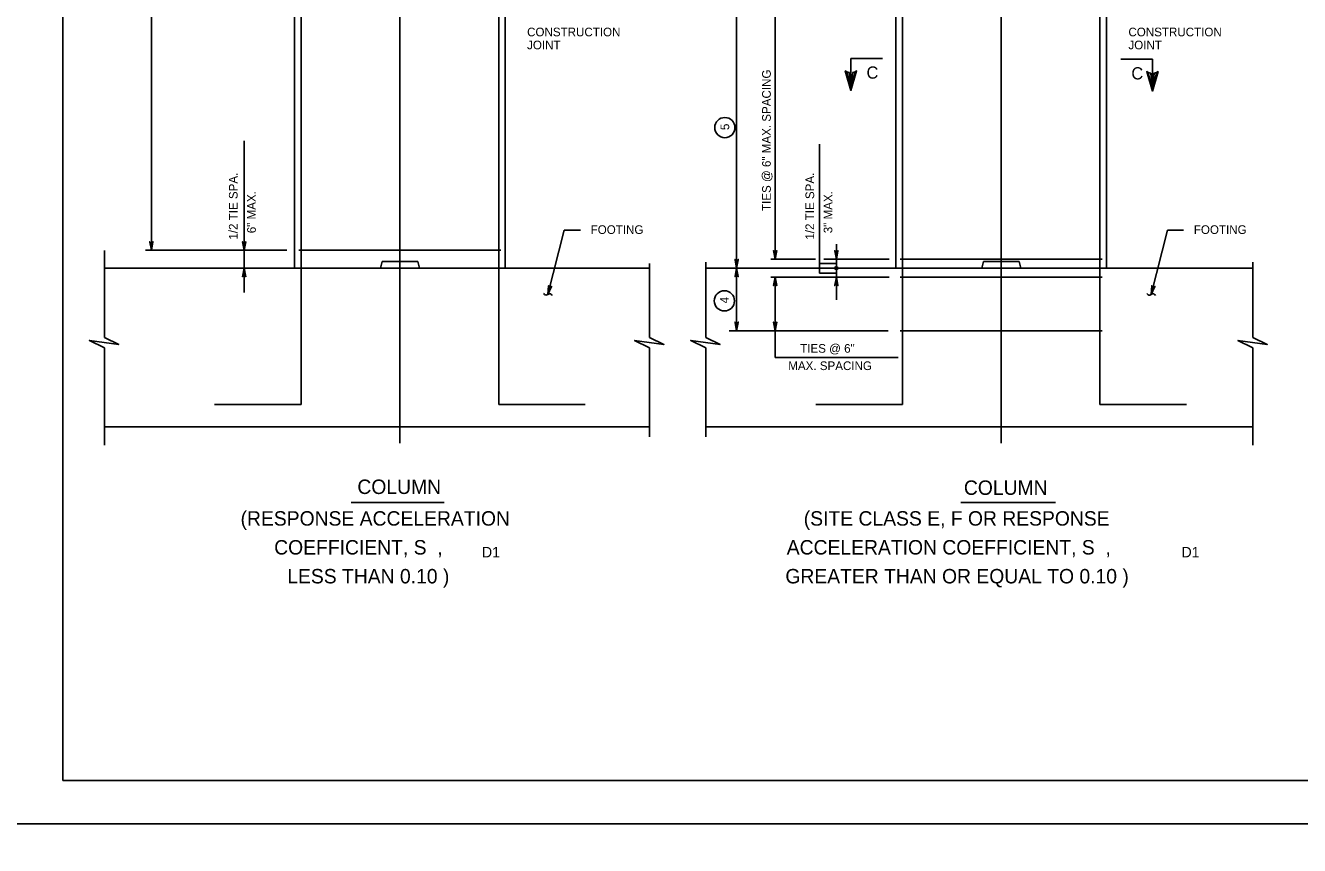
# Model space of a CAD drawing. Extents: x 646165 to 651486, y 296916 to 299292.
# Drawn here: x 649816.7 to 650257.8, y 298096.8 to 298380.6 of the extents above; entities that cross this region are included whole.
import ezdxf

# ---------------------------------------------------------------- set-up
doc = ezdxf.new("R2010")
doc.units = 0
for name, color, linetype in [('1', 7, 'Continuous'), ('2', 7, 'Continuous'), ('50', 7, 'Continuous'), ('51', 7, 'Continuous'), ('52', 7, 'Continuous'), ('53', 7, 'Continuous'), ('54', 7, 'Continuous'), ('PLT-BNDY', 7, 'Continuous')]:
    doc.layers.add(name, color=color, linetype=linetype)

msp = doc.modelspace()

# ---------------------------------------------------------------- linework, layer by layer
at = {"layer": '1'}
for p, q in [((650102.47, 298369.22), (650113.39, 298369.22)), ((650102.47, 298358.15), (650102.47, 298369.22)), ((650206.88, 298368.95), (650195.96, 298368.95)), ((650206.88, 298357.88), (650206.88, 298368.95))]:
    msp.add_line(p, q, dxfattribs=at)
for points in [[(650103.94, 298364.57), (650103.09, 298364.33), (650102.47, 298358.15), (650103.94, 298364.57), (650104.45, 298364.9), (650102.47, 298358.15), (650101.91, 298364.33), (650101.07, 298364.55), (650102.47, 298358.15), (650100.52, 298364.9), (650101.07, 298364.55)], [(650205.41, 298364.3), (650206.26, 298364.07), (650206.88, 298357.88), (650205.41, 298364.3), (650204.89, 298364.63), (650206.88, 298357.88), (650207.44, 298364.06), (650208.27, 298364.29), (650206.88, 298357.88), (650208.83, 298364.63), (650208.27, 298364.29)]]:
    msp.add_lwpolyline(points, dxfattribs=at)
at = {"layer": '2'}
for p, q in [((649829.59, 298119.25), (649829.59, 298683.25)), ((650615.59, 298119.25), (649829.59, 298119.25))]:
    msp.add_line(p, q, dxfattribs=at)
at = {"layer": '50'}
for p, q in [((649946.33, 298602.2), (649946.33, 298236.03)), ((650154.51, 298602.2), (650154.51, 298236.03))]:
    msp.add_line(p, q, dxfattribs=at)
at = {"layer": '51'}
for p, q in [((649909.88, 298430.58), (649909.88, 298296.63)), ((649982.78, 298430.58), (649982.78, 298296.63)), ((650118.06, 298430.58), (650118.06, 298296.63)), ((650190.96, 298430.58), (650190.96, 298296.63)), ((649844.05, 298296.63), (650032.79, 298296.63)), ((649940.16, 298298.88), (649939.58, 298296.63)), ((649940.16, 298298.88), (649952.5, 298298.88)), ((649952.5, 298298.88), (649953.08, 298296.63)), ((650052.23, 298296.63), (650241.62, 298296.63)), ((650148.34, 298298.88), (650147.76, 298296.63)), ((650148.34, 298298.88), (650160.68, 298298.88)), ((650160.68, 298298.88), (650161.26, 298296.63)), ((649844.05, 298241.73), (650032.79, 298241.73)), ((650052.23, 298241.73), (650241.62, 298241.73))]:
    msp.add_line(p, q, dxfattribs=at)
at = {"layer": '52'}
for p, q in [((649860.29, 298560.63), (649860.29, 298302.78)), ((650076.27, 298560.63), (650076.27, 298299.7)), ((650062.91, 298398.45), (650062.91, 298274.96)), ((649892.42, 298340.72), (649892.42, 298288.23)), ((650091.64, 298339.58), (650091.64, 298294.9)), ((650003.24, 298309.74), (649997.59, 298287.5)), ((650003.24, 298309.74), (650008.83, 298309.74)), ((650212.08, 298309.74), (650206.42, 298287.5)), ((650212.08, 298309.74), (650217.66, 298309.74)), ((649844.05, 298302.74), (649844.05, 298272.55)), ((649858.24, 298302.78), (649907.15, 298302.78)), ((650097.43, 298304.96), (650097.43, 298285.69)), ((650032.79, 298298.2), (650032.79, 298272.55)), ((650052.23, 298298.63), (650052.23, 298272.55)), ((650090.22, 298299.7), (650074.79, 298299.7)), ((650097.43, 298298.23), (650091.64, 298298.23)), ((650115.76, 298299.7), (650093.09, 298299.7)), ((650241.62, 298298.63), (650241.62, 298272.55)), ((650115.76, 298293.54), (650074.79, 298293.54)), ((650076.27, 298293.54), (650076.27, 298265.65)), ((650097.43, 298294.9), (650091.64, 298294.9)), ((650060.29, 298274.96), (650115.33, 298274.96)), ((649844.05, 298269.03), (649844.05, 298235.31)), ((650032.79, 298269.03), (650032.79, 298238.17)), ((650052.23, 298269.03), (650052.23, 298238.17)), ((650241.62, 298269.03), (650241.62, 298235.31)), ((650076.27, 298265.65), (650118.8, 298265.65))]:
    msp.add_line(p, q, dxfattribs=at)
for points in [[(649860.29, 298302.78), (649859.73, 298305.76), (649859.81, 298305.65), (649859.89, 298305.53), (649859.99, 298305.48), (649860.09, 298305.42), (649860.19, 298305.4), (649860.29, 298305.38), (649860.39, 298305.4), (649860.49, 298305.42), (649860.59, 298305.48), (649860.69, 298305.53), (649860.77, 298305.65), (649860.85, 298305.76), (649860.29, 298302.78), (649860.77, 298305.65), (649860.69, 298305.53), (649860.29, 298302.78), (649860.59, 298305.48), (649860.49, 298305.42), (649860.29, 298302.78), (649860.39, 298305.4), (649860.29, 298305.38), (649860.29, 298302.78), (649860.19, 298305.4), (649860.09, 298305.42), (649860.29, 298302.78), (649859.99, 298305.48), (649859.89, 298305.53), (649860.29, 298302.78), (649859.81, 298305.65)], [(649892.42, 298302.78), (649891.86, 298305.76), (649891.94, 298305.65), (649892.02, 298305.53), (649892.12, 298305.48), (649892.22, 298305.42), (649892.32, 298305.4), (649892.42, 298305.38), (649892.52, 298305.4), (649892.62, 298305.42), (649892.72, 298305.48), (649892.82, 298305.53), (649892.9, 298305.65), (649892.98, 298305.76), (649892.42, 298302.78), (649892.9, 298305.65), (649892.82, 298305.53), (649892.42, 298302.78), (649892.72, 298305.48), (649892.62, 298305.42), (649892.42, 298302.78), (649892.52, 298305.4), (649892.42, 298305.38), (649892.42, 298302.78), (649892.32, 298305.4), (649892.22, 298305.42), (649892.42, 298302.78), (649892.12, 298305.48), (649892.02, 298305.53), (649892.42, 298302.78), (649891.94, 298305.65)], [(650076.27, 298299.7), (650075.71, 298302.69), (650075.79, 298302.57), (650075.87, 298302.46), (650075.97, 298302.4), (650076.07, 298302.34), (650076.17, 298302.32), (650076.27, 298302.3), (650076.37, 298302.32), (650076.47, 298302.34), (650076.57, 298302.4), (650076.67, 298302.46), (650076.74, 298302.57), (650076.82, 298302.69), (650076.27, 298299.7), (650076.74, 298302.57), (650076.67, 298302.46), (650076.27, 298299.7), (650076.57, 298302.4), (650076.47, 298302.34), (650076.27, 298299.7), (650076.37, 298302.32), (650076.27, 298302.3), (650076.27, 298299.7), (650076.17, 298302.32), (650076.07, 298302.34), (650076.27, 298299.7), (650075.97, 298302.4), (650075.87, 298302.46), (650076.27, 298299.7), (650075.79, 298302.57)], [(650097.43, 298299.7), (650097.99, 298302.69), (650097.91, 298302.57), (650097.83, 298302.46), (650097.73, 298302.4), (650097.63, 298302.34), (650097.53, 298302.32), (650097.43, 298302.3), (650097.33, 298302.32), (650097.23, 298302.34), (650097.13, 298302.4), (650097.03, 298302.46), (650096.96, 298302.57), (650096.88, 298302.69), (650097.43, 298299.7), (650096.96, 298302.57), (650097.03, 298302.46), (650097.43, 298299.7), (650097.13, 298302.4), (650097.23, 298302.34), (650097.43, 298299.7), (650097.33, 298302.32), (650097.43, 298302.3), (650097.43, 298299.7), (650097.53, 298302.32), (650097.63, 298302.34), (650097.43, 298299.7), (650097.73, 298302.4), (650097.83, 298302.46), (650097.43, 298299.7), (650097.91, 298302.57)], [(649892.42, 298296.63), (649892.98, 298293.64), (649892.9, 298293.76), (649892.82, 298293.87), (649892.72, 298293.93), (649892.62, 298293.99), (649892.52, 298294.01), (649892.42, 298294.03), (649892.32, 298294.01), (649892.22, 298293.99), (649892.12, 298293.93), (649892.02, 298293.87), (649891.94, 298293.76), (649891.86, 298293.64), (649892.42, 298296.63), (649891.94, 298293.76), (649892.02, 298293.87), (649892.42, 298296.63), (649892.12, 298293.93), (649892.22, 298293.99), (649892.42, 298296.63), (649892.32, 298294.01), (649892.42, 298294.03), (649892.42, 298296.63), (649892.52, 298294.01), (649892.62, 298293.99), (649892.42, 298296.63), (649892.72, 298293.93), (649892.82, 298293.87), (649892.42, 298296.63), (649892.9, 298293.76)], [(650062.91, 298296.63), (650063.47, 298299.61), (650063.39, 298299.49), (650063.31, 298299.38), (650063.21, 298299.32), (650063.11, 298299.26), (650063.01, 298299.24), (650062.91, 298299.23), (650062.81, 298299.24), (650062.71, 298299.26), (650062.61, 298299.32), (650062.51, 298299.38), (650062.43, 298299.49), (650062.35, 298299.61), (650062.91, 298296.63), (650062.43, 298299.49), (650062.51, 298299.38), (650062.91, 298296.63), (650062.61, 298299.32), (650062.71, 298299.26), (650062.91, 298296.63), (650062.81, 298299.24), (650062.91, 298299.23), (650062.91, 298296.63), (650063.01, 298299.24), (650063.11, 298299.26), (650062.91, 298296.63), (650063.21, 298299.32), (650063.31, 298299.38), (650062.91, 298296.63), (650063.39, 298299.49)], [(650062.91, 298296.63), (650063.47, 298293.64), (650063.39, 298293.76), (650063.31, 298293.87), (650063.21, 298293.93), (650063.11, 298293.99), (650063.01, 298294.01), (650062.91, 298294.03), (650062.81, 298294.01), (650062.71, 298293.99), (650062.61, 298293.93), (650062.51, 298293.87), (650062.43, 298293.76), (650062.35, 298293.64), (650062.91, 298296.63), (650062.43, 298293.76), (650062.51, 298293.87), (650062.91, 298296.63), (650062.61, 298293.93), (650062.71, 298293.99), (650062.91, 298296.63), (650062.81, 298294.01), (650062.91, 298294.03), (650062.91, 298296.63), (650063.01, 298294.01), (650063.11, 298293.99), (650062.91, 298296.63), (650063.21, 298293.93), (650063.31, 298293.87), (650062.91, 298296.63), (650063.39, 298293.76)], [(650076.27, 298293.54), (650076.82, 298290.56), (650076.74, 298290.68), (650076.67, 298290.79), (650076.57, 298290.85), (650076.47, 298290.91), (650076.37, 298290.93), (650076.27, 298290.94), (650076.17, 298290.93), (650076.07, 298290.91), (650075.97, 298290.85), (650075.87, 298290.79), (650075.79, 298290.68), (650075.71, 298290.56), (650076.27, 298293.54), (650075.79, 298290.68), (650075.87, 298290.79), (650076.27, 298293.54), (650075.97, 298290.85), (650076.07, 298290.91), (650076.27, 298293.54), (650076.17, 298290.93), (650076.27, 298290.94), (650076.27, 298293.54), (650076.37, 298290.93), (650076.47, 298290.91), (650076.27, 298293.54), (650076.57, 298290.85), (650076.67, 298290.79), (650076.27, 298293.54), (650076.74, 298290.68)], [(650097.43, 298293.54), (650096.88, 298290.56), (650096.96, 298290.68), (650097.03, 298290.79), (650097.13, 298290.85), (650097.23, 298290.91), (650097.33, 298290.93), (650097.43, 298290.94), (650097.53, 298290.93), (650097.63, 298290.91), (650097.73, 298290.85), (650097.83, 298290.79), (650097.91, 298290.68), (650097.99, 298290.56), (650097.43, 298293.54), (650097.91, 298290.68), (650097.83, 298290.79), (650097.43, 298293.54), (650097.73, 298290.85), (650097.63, 298290.91), (650097.43, 298293.54), (650097.53, 298290.93), (650097.43, 298290.94), (650097.43, 298293.54), (650097.33, 298290.93), (650097.23, 298290.91), (650097.43, 298293.54), (650097.13, 298290.85), (650097.03, 298290.79), (650097.43, 298293.54), (650096.96, 298290.68)], [(649997.59, 298287.5), (649997.78, 298290.53), (649997.83, 298290.4), (649997.88, 298290.27), (649997.96, 298290.19), (649998.04, 298290.11), (649998.14, 298290.07), (649998.23, 298290.02), (649998.33, 298290.02), (649998.43, 298290.01), (649998.54, 298290.04), (649998.65, 298290.07), (649998.76, 298290.17), (649998.87, 298290.26), (649997.59, 298287.5), (649998.76, 298290.17), (649998.65, 298290.07), (649997.59, 298287.5), (649998.54, 298290.04), (649998.43, 298290.01), (649997.59, 298287.5), (649998.33, 298290.02), (649998.23, 298290.02), (649997.59, 298287.5), (649998.14, 298290.07), (649998.04, 298290.11), (649997.59, 298287.5), (649997.96, 298290.19), (649997.88, 298290.27), (649997.59, 298287.5), (649997.83, 298290.4)], [(650206.42, 298287.5), (650206.62, 298290.53), (650206.66, 298290.4), (650206.71, 298290.27), (650206.8, 298290.19), (650206.88, 298290.11), (650206.97, 298290.07), (650207.06, 298290.02), (650207.16, 298290.02), (650207.27, 298290.01), (650207.38, 298290.04), (650207.49, 298290.07), (650207.59, 298290.17), (650207.7, 298290.26), (650206.42, 298287.5), (650207.59, 298290.17), (650207.49, 298290.07), (650206.42, 298287.5), (650207.38, 298290.04), (650207.27, 298290.01), (650206.42, 298287.5), (650207.16, 298290.02), (650207.06, 298290.02), (650206.42, 298287.5), (650206.97, 298290.07), (650206.88, 298290.11), (650206.42, 298287.5), (650206.8, 298290.19), (650206.71, 298290.27), (650206.42, 298287.5), (650206.66, 298290.4)], [(650062.91, 298274.96), (650062.35, 298277.94), (650062.43, 298277.83), (650062.51, 298277.71), (650062.61, 298277.65), (650062.71, 298277.59), (650062.81, 298277.58), (650062.91, 298277.56), (650063.01, 298277.58), (650063.11, 298277.59), (650063.21, 298277.65), (650063.31, 298277.71), (650063.39, 298277.83), (650063.47, 298277.94), (650062.91, 298274.96), (650063.39, 298277.83), (650063.31, 298277.71), (650062.91, 298274.96), (650063.21, 298277.65), (650063.11, 298277.59), (650062.91, 298274.96), (650063.01, 298277.58), (650062.91, 298277.56), (650062.91, 298274.96), (650062.81, 298277.58), (650062.71, 298277.59), (650062.91, 298274.96), (650062.61, 298277.65), (650062.51, 298277.71), (650062.91, 298274.96), (650062.43, 298277.83)], [(650062.91, 298274.96), (650062.35, 298277.94), (650062.43, 298277.83), (650062.51, 298277.71), (650062.61, 298277.65), (650062.71, 298277.59), (650062.81, 298277.58), (650062.91, 298277.56), (650063.01, 298277.58), (650063.11, 298277.59), (650063.21, 298277.65), (650063.31, 298277.71), (650063.39, 298277.83), (650063.47, 298277.94), (650062.91, 298274.96), (650063.39, 298277.83), (650063.31, 298277.71), (650062.91, 298274.96), (650063.21, 298277.65), (650063.11, 298277.59), (650062.91, 298274.96), (650063.01, 298277.58), (650062.91, 298277.56), (650062.91, 298274.96), (650062.81, 298277.58), (650062.71, 298277.59), (650062.91, 298274.96), (650062.61, 298277.65), (650062.51, 298277.71), (650062.91, 298274.96), (650062.43, 298277.83)], [(650076.27, 298274.96), (650075.71, 298277.94), (650075.79, 298277.83), (650075.87, 298277.71), (650075.97, 298277.65), (650076.07, 298277.59), (650076.17, 298277.58), (650076.27, 298277.56), (650076.37, 298277.58), (650076.47, 298277.59), (650076.57, 298277.65), (650076.67, 298277.71), (650076.74, 298277.83), (650076.82, 298277.94), (650076.27, 298274.96), (650076.74, 298277.83), (650076.67, 298277.71), (650076.27, 298274.96), (650076.57, 298277.65), (650076.47, 298277.59), (650076.27, 298274.96), (650076.37, 298277.58), (650076.27, 298277.56), (650076.27, 298274.96), (650076.17, 298277.58), (650076.07, 298277.59), (650076.27, 298274.96), (650075.97, 298277.65), (650075.87, 298277.71), (650076.27, 298274.96), (650075.79, 298277.83)], [(649844.05, 298269.03), (649838.87, 298271.57), (649849.02, 298270.19), (649844.05, 298272.55)], [(650032.79, 298269.03), (650027.61, 298271.57), (650037.75, 298270.19), (650032.79, 298272.55)], [(650052.23, 298269.03), (650047.05, 298271.57), (650057.19, 298270.19), (650052.23, 298272.55)], [(650241.62, 298269.03), (650236.44, 298271.57), (650246.59, 298270.19), (650241.62, 298272.55)]]:
    msp.add_lwpolyline(points, dxfattribs=at)
for centre, radius in [((650058.84, 298345.26), 3.5), ((650097.43, 298296.63), 0.533), ((650097.43, 298296.63), 0.267), ((650058.67, 298285.28), 3.5)]:
    msp.add_circle(centre, radius, dxfattribs=at)
for points in [[(649999.09, 298287.09), (649998.37, 298287.75), (649996.8, 298287.26), (649996.08, 298287.87)], [(650207.93, 298287.09), (650207.2, 298287.75), (650205.63, 298287.26), (650204.91, 298287.87)]]:
    msp.add_spline(points, degree=3, dxfattribs=at)
at = {"layer": '53'}
for p, q in [((649929.45, 298215.53), (649961.63, 298215.53)), ((650140.56, 298215.53), (650173.34, 298215.53))]:
    msp.add_line(p, q, dxfattribs=at)
at = {"layer": '54'}
for p, q in [((649912.13, 298427.99), (649912.13, 298249.41)), ((649980.53, 298427.99), (649980.53, 298249.41)), ((650120.31, 298427.99), (650120.31, 298249.41)), ((650188.71, 298427.99), (650188.71, 298249.41)), ((649911.38, 298302.78), (649981.28, 298302.78)), ((650119.56, 298299.7), (650189.46, 298299.7)), ((650119.56, 298293.54), (650189.46, 298293.54)), ((650119.56, 298274.96), (650189.46, 298274.96)), ((649882.13, 298249.41), (649912.13, 298249.41)), ((649980.53, 298249.41), (650010.53, 298249.41)), ((650090.31, 298249.41), (650120.31, 298249.41)), ((650188.71, 298249.41), (650218.71, 298249.41))]:
    msp.add_line(p, q, dxfattribs=at)
at = {"layer": 'PLT-BNDY'}
for points in [[(649789.59, 298698.25), (650630.59, 298698.25), (650630.59, 298104.25), (649789.59, 298104.25)], [(649789.59, 298104.25), (650630.59, 298104.25), (650630.59, 297510.25), (649789.59, 297510.25)]]:
    msp.add_lwpolyline(points, close=True, dxfattribs=at)

# ---------------------------------------------------------------- texts
at = {"layer": '1'}
for p in [(650107.88, 298362.2), (650199.58, 298361.94)]:
    msp.add_text('C', height=4.23, dxfattribs=at).set_placement(p)
at = {"layer": '53'}
for s, height, p in [('CONSTRUCTION', 3, (649990.37, 298376.86)), ('CONSTRUCTION', 3, (650198.55, 298376.86)), ('JOINT', 3, (649990.37, 298372.36)), ('JOINT', 3, (650198.55, 298372.36)), ('FOOTING', 3, (650012.37, 298308.45)), ('FOOTING', 3, (650221.2, 298308.45)), ('TIES @ 6"', 3, (650084.91, 298267.33)), ('MAX. SPACING', 3, (650080.78, 298261.33)), ('COLUMN', 5, (649931.61, 298218.43)), ('COLUMN', 5, (650141.59, 298218.13)), ('(RESPONSE ACCELERATION', 5, (649891.17, 298207.48)), ('(SITE CLASS E, F OR RESPONSE', 5, (650086.15, 298207.48)), ('COEFFICIENT, S  ,', 5, (649902.81, 298197.48)), ('D1', 3.63, (649974.76, 298196.49)), ('ACCELERATION COEFFICIENT, S  ,', 5, (650080.26, 298197.48)), ('D1', 3.63, (650216.95, 298196.49)), ('LESS THAN 0.10 )', 5, (649907.34, 298187.48)), ('GREATER THAN OR EQUAL TO 0.10 )', 5, (650079.79, 298187.48))]:
    msp.add_text(s, height=height, dxfattribs=at).set_placement(p)
for s, p in [('TIES @ 6" MAX. SPACING', (650074.74, 298316.39)), ('5', (650060.34, 298344.41)), ('1/2 TIE SPA.', (649890.15, 298306.47)), ('1/2 TIE SPA.', (650089.75, 298306.47)), ('  6" MAX.', (649896.45, 298306.47)), ('  3" MAX.', (650096.05, 298306.47)), ('4', (650060.17, 298284.43))]:
    msp.add_text(s, height=3, rotation=90, dxfattribs=at).set_placement(p)

doc.saveas('drawing.dxf')
